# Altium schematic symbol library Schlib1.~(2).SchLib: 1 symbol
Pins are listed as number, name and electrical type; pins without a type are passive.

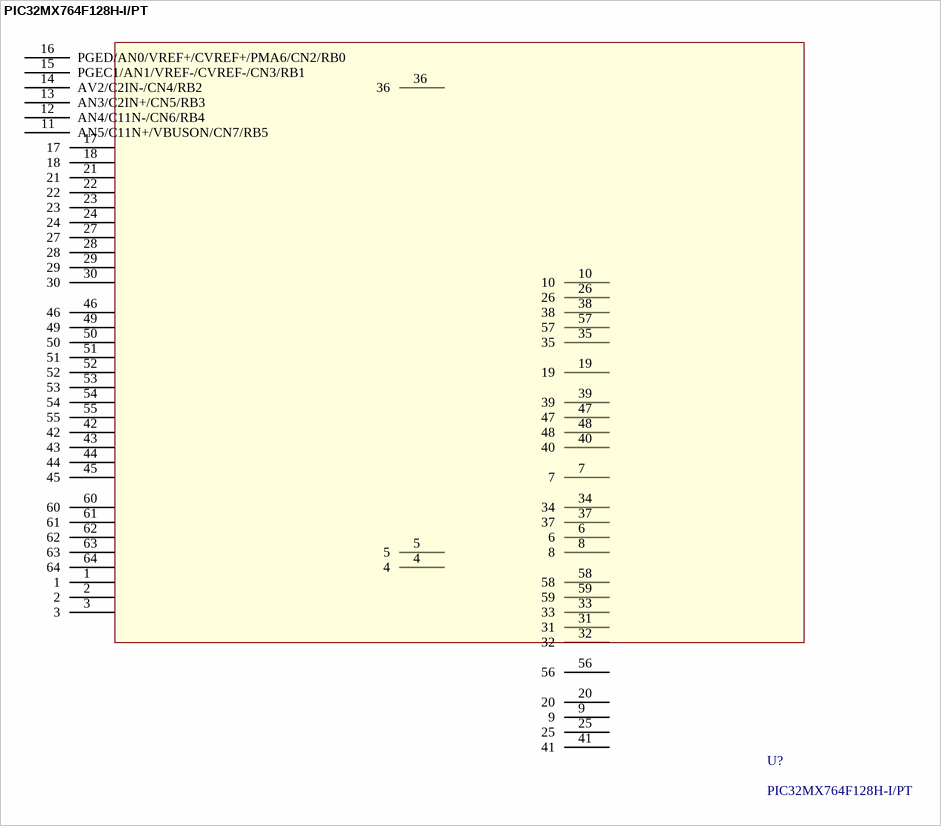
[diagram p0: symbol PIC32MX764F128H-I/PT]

## PIC32MX764F128H-I/PT
designator U?
Fabricant: Microchip; Fournisseur: Farnell; RefFournisseur: 1971889
pins: 1, 2, 3, 4, 5, 6, 7, 8, 9, 10, 11 AN5/C11N+/VBUSON/CN7/RB5, 12 AN4/C11N-/CN6/RB4, 13 AN3/C2IN+/CN5/RB3, 14 AV2/C2IN-/CN4/RB2, 15 PGEC1/AN1/VREF-/CVREF-/CN3/RB1, 16 PGED/AN0/VREF+/CVREF+/PMA6/CN2/RB0, 17, 18, 19, 20, 21, 22, 23, 24, 25, 26, 27, 28, 29, 30, 31, 32, 33, 34, 35, 36, 37, 38, 39, 40, 41, 42, 43, 44, 45, 46, 47, 48, 49, 50, 51, 52, 53, 54, 55, 56, 57, 58, 59, 60, 61, 62, 63, 64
